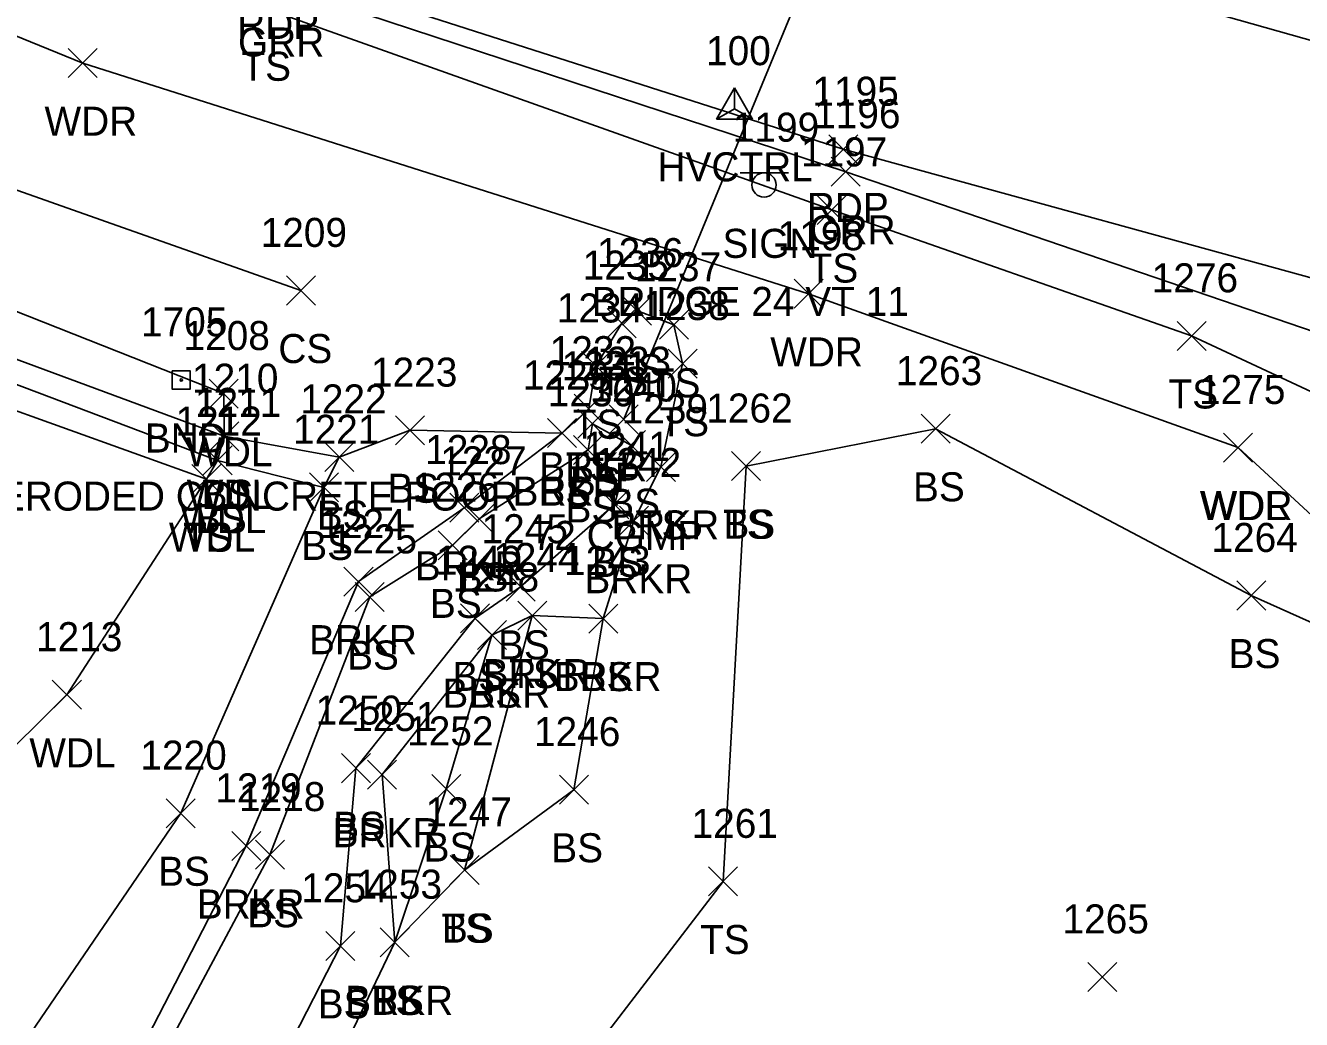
# Model space of a CAD drawing. Extents: x 1547013 to 1549434, y 267998 to 268739.
# Drawn here: x 1548511.9 to 1548599.8, y 268039.5 to 268107.9 of the extents above; entities that cross this region are included whole.
import ezdxf

# ---------------------------------------------------------------- set-up
doc = ezdxf.new("R2010")
doc.units = 0
for name, color, linetype in [('C_A', 7, 'Continuous'), ('C_I', 7, 'Continuous'), ('CPSM', 7, 'Continuous'), ('D_A', 7, 'Continuous'), ('D_C', 7, 'Continuous'), ('D_I', 7, 'Continuous'), ('D_TIC', 7, 'Continuous'), ('DCP', 7, 'Continuous'), ('L_A', 7, 'Continuous'), ('L_I', 7, 'Continuous'), ('L_TIC', 7, 'Continuous'), ('LAWA', 7, 'Continuous'), ('LAWE', 7, 'Continuous'), ('LELB', 7, 'Continuous'), ('M_A', 7, 'Continuous'), ('M_C', 7, 'Continuous'), ('M_I', 7, 'Continuous'), ('MHBP', 7, 'Continuous'), ('P_A', 7, 'Continuous'), ('P_I', 7, 'Continuous'), ('P_TIC', 7, 'Continuous'), ('PET', 7, 'Continuous'), ('PRC', 7, 'Continuous'), ('R_A', 7, 'Continuous'), ('R_I', 7, 'Continuous'), ('R_TIC', 7, 'Continuous'), ('RGR', 7, 'Continuous'), ('S_A', 7, 'Continuous'), ('S_C', 7, 'Continuous'), ('S_I', 7, 'Continuous'), ('SSGN', 7, 'Continuous')]:
    doc.layers.add(name, color=color, linetype=linetype)

msp = doc.modelspace()

# ---------------------------------------------------------------- linework, layer by layer
at = {"layer": 'CPSM'}
for p, q in [((1548559.462, 268101.487), (1548560.712, 268103.652)), ((1548559.462, 268101.487), (1548560.712, 268103.652)), ((1548561.962, 268101.487), (1548560.712, 268103.652)), ((1548560.713, 268102.208), (1548560.712, 268103.652)), ((1548561.962, 268101.487), (1548560.712, 268103.652)), ((1548560.713, 268102.208), (1548560.712, 268103.652)), ((1548559.462, 268101.487), (1548560.713, 268102.208)), ((1548559.462, 268101.487), (1548560.713, 268102.208)), ((1548560.713, 268102.208), (1548560.713, 268102.208)), ((1548560.713, 268102.208), (1548561.962, 268101.487)), ((1548560.713, 268102.208), (1548560.713, 268102.208)), ((1548560.713, 268102.208), (1548561.962, 268101.487)), ((1548559.462, 268101.487), (1548561.962, 268101.487)), ((1548559.462, 268101.487), (1548561.962, 268101.487))]:
    msp.add_line(p, q, dxfattribs=at)
at = {"layer": 'D_TIC'}
for points in [[(1548552.082, 268079.82), (1548554.082, 268081.82)], [(1548554.082, 268079.82), (1548552.082, 268081.82)]]:
    msp.add_lwpolyline(points, dxfattribs=at)
at = {"layer": 'DCP'}
msp.add_lwpolyline([(1548553.082, 268080.82), (1548581.569, 268149.791)], dxfattribs=at)
at = {"layer": 'L_TIC'}
for points in [[(1548514.817, 268104.352), (1548516.817, 268106.352)], [(1548516.817, 268104.352), (1548514.817, 268106.352)], [(1548566.412, 268094.236), (1548568.412, 268096.236)], [(1548568.412, 268094.236), (1548566.412, 268096.236)], [(1548529.847, 268088.689), (1548531.847, 268090.689)], [(1548531.847, 268088.689), (1548529.847, 268090.689)], [(1548564.814, 268088.461), (1548566.814, 268090.461)], [(1548566.814, 268088.461), (1548564.814, 268090.461)], [(1548552.994, 268087.3), (1548554.994, 268089.3)], [(1548554.994, 268087.3), (1548552.994, 268089.3)], [(1548551.944, 268086.439), (1548553.944, 268088.439)], [(1548553.944, 268086.439), (1548551.944, 268088.439)], [(1548555.538, 268086.326), (1548557.538, 268088.326)], [(1548557.538, 268086.326), (1548555.538, 268088.326)], [(1548591.201, 268085.561), (1548593.201, 268087.561)], [(1548593.201, 268085.561), (1548591.201, 268087.561)], [(1548550.163, 268083.485), (1548552.163, 268085.485)], [(1548552.163, 268083.485), (1548550.163, 268085.485)], [(1548556.133, 268083.65), (1548558.133, 268085.65)], [(1548558.133, 268083.65), (1548556.133, 268085.65)], [(1548524.525, 268081.584), (1548526.525, 268083.584)], [(1548526.525, 268081.584), (1548524.525, 268083.584)], [(1548549.675, 268080.543), (1548551.675, 268082.543)], [(1548551.675, 268080.543), (1548549.675, 268082.543)], [(1548549.675, 268080.543), (1548551.675, 268082.543)], [(1548551.675, 268080.543), (1548549.675, 268082.543)], [(1548537.362, 268079.066), (1548539.362, 268081.066)], [(1548539.362, 268079.066), (1548537.362, 268081.066)], [(1548549.929, 268079.508), (1548551.929, 268081.508)], [(1548551.929, 268079.508), (1548549.929, 268081.508)], [(1548573.568, 268079.167), (1548575.568, 268081.167)], [(1548575.568, 268079.167), (1548573.568, 268081.167)], [(1548524.556, 268078.648), (1548526.556, 268080.648)], [(1548526.556, 268078.648), (1548524.556, 268080.648)], [(1548524.556, 268078.648), (1548526.556, 268080.648)], [(1548526.556, 268078.648), (1548524.556, 268080.648)], [(1548547.832, 268078.869), (1548549.832, 268080.869)], [(1548549.832, 268078.869), (1548547.832, 268080.869)], [(1548547.832, 268078.869), (1548549.832, 268080.869)], [(1548549.832, 268078.869), (1548547.832, 268080.869)], [(1548532.489, 268077.219), (1548534.489, 268079.219)], [(1548534.489, 268077.219), (1548532.489, 268079.219)], [(1548532.489, 268077.219), (1548534.489, 268079.219)], [(1548534.489, 268077.219), (1548532.489, 268079.219)], [(1548549.63, 268077.711), (1548551.63, 268079.711)], [(1548551.63, 268077.711), (1548549.63, 268079.711)], [(1548552.575, 268078.042), (1548554.575, 268080.042)], [(1548554.575, 268078.042), (1548552.575, 268080.042)], [(1548594.409, 268077.871), (1548596.409, 268079.871)], [(1548596.409, 268077.871), (1548594.409, 268079.871)], [(1548594.409, 268077.871), (1548596.409, 268079.871)], [(1548596.409, 268077.871), (1548594.409, 268079.871)], [(1548524.104, 268076.981), (1548526.104, 268078.981)], [(1548526.104, 268076.981), (1548524.104, 268078.981)], [(1548524.104, 268076.981), (1548526.104, 268078.981)], [(1548526.104, 268076.981), (1548524.104, 268078.981)], [(1548554.64, 268076.538), (1548556.64, 268078.538)], [(1548556.64, 268076.538), (1548554.64, 268078.538)], [(1548554.64, 268076.538), (1548556.64, 268078.538)], [(1548556.64, 268076.538), (1548554.64, 268078.538)], [(1548560.508, 268076.593), (1548562.508, 268078.593)], [(1548562.508, 268076.593), (1548560.508, 268078.593)], [(1548560.508, 268076.593), (1548562.508, 268078.593)], [(1548562.508, 268076.593), (1548560.508, 268078.593)], [(1548523.33, 268075.697), (1548525.33, 268077.697)], [(1548525.33, 268075.697), (1548523.33, 268077.697)], [(1548523.33, 268075.697), (1548525.33, 268077.697)], [(1548525.33, 268075.697), (1548523.33, 268077.697)], [(1548531.424, 268075.127), (1548533.424, 268077.127)], [(1548533.424, 268075.127), (1548531.424, 268077.127)], [(1548531.424, 268075.127), (1548533.424, 268077.127)], [(1548533.424, 268075.127), (1548531.424, 268077.127)], [(1548541.097, 268073.729), (1548543.097, 268075.729)], [(1548543.097, 268073.729), (1548541.097, 268075.729)], [(1548551.435, 268073.954), (1548553.435, 268075.954)], [(1548553.435, 268073.954), (1548551.435, 268075.954)], [(1548542.133, 268072.957), (1548544.133, 268074.957)], [(1548544.133, 268072.957), (1548542.133, 268074.957)], [(1548552.783, 268072.836), (1548554.783, 268074.836)], [(1548554.783, 268072.836), (1548552.783, 268074.836)], [(1548540.29, 268071.138), (1548542.29, 268073.138)], [(1548542.29, 268071.138), (1548540.29, 268073.138)], [(1548533.81, 268068.637), (1548535.81, 268070.637)], [(1548535.81, 268068.637), (1548533.81, 268070.637)], [(1548534.584, 268067.58), (1548536.584, 268069.58)], [(1548536.584, 268067.58), (1548534.584, 268069.58)], [(1548544.979, 268068.28), (1548546.979, 268070.28)], [(1548546.979, 268068.28), (1548544.979, 268070.28)], [(1548595.314, 268067.68), (1548597.314, 268069.68)], [(1548597.314, 268067.68), (1548595.314, 268069.68)], [(1548541.836, 268066.108), (1548543.836, 268068.108)], [(1548543.836, 268066.108), (1548541.836, 268068.108)], [(1548545.778, 268066.299), (1548547.778, 268068.299)], [(1548547.778, 268066.299), (1548545.778, 268068.299)], [(1548545.778, 268066.299), (1548547.778, 268068.299)], [(1548547.778, 268066.299), (1548545.778, 268068.299)], [(1548550.667, 268066.092), (1548552.667, 268068.092)], [(1548552.667, 268066.092), (1548550.667, 268068.092)], [(1548550.667, 268066.092), (1548552.667, 268068.092)], [(1548552.667, 268066.092), (1548550.667, 268068.092)], [(1548542.997, 268064.954), (1548544.997, 268066.954)], [(1548544.997, 268064.954), (1548542.997, 268066.954)], [(1548542.997, 268064.954), (1548544.997, 268066.954)], [(1548544.997, 268064.954), (1548542.997, 268066.954)], [(1548513.716, 268060.844), (1548515.716, 268062.844)], [(1548515.716, 268060.844), (1548513.716, 268062.844)], [(1548533.631, 268055.786), (1548535.631, 268057.786)], [(1548535.631, 268055.786), (1548533.631, 268057.786)], [(1548535.438, 268055.344), (1548537.438, 268057.344)], [(1548537.438, 268055.344), (1548535.438, 268057.344)], [(1548539.853, 268054.353), (1548541.853, 268056.353)], [(1548541.853, 268054.353), (1548539.853, 268056.353)], [(1548548.648, 268054.306), (1548550.648, 268056.306)], [(1548550.648, 268054.306), (1548548.648, 268056.306)], [(1548521.561, 268052.685), (1548523.561, 268054.685)], [(1548523.561, 268052.685), (1548521.561, 268054.685)], [(1548526.076, 268050.43), (1548528.076, 268052.43)], [(1548528.076, 268050.43), (1548526.076, 268052.43)], [(1548527.703, 268049.828), (1548529.703, 268051.828)], [(1548529.703, 268049.828), (1548527.703, 268051.828)], [(1548541.115, 268048.77), (1548543.115, 268050.77)], [(1548543.115, 268048.77), (1548541.115, 268050.77)], [(1548541.115, 268048.77), (1548543.115, 268050.77)], [(1548543.115, 268048.77), (1548541.115, 268050.77)], [(1548558.928, 268047.986), (1548560.928, 268049.986)], [(1548560.928, 268047.986), (1548558.928, 268049.986)], [(1548532.559, 268043.548), (1548534.559, 268045.548)], [(1548534.559, 268043.548), (1548532.559, 268045.548)], [(1548536.305, 268043.796), (1548538.305, 268045.796)], [(1548538.305, 268043.796), (1548536.305, 268045.796)], [(1548536.305, 268043.796), (1548538.305, 268045.796)], [(1548538.305, 268043.796), (1548536.305, 268045.796)], [(1548536.305, 268043.796), (1548538.305, 268045.796)], [(1548538.305, 268043.796), (1548536.305, 268045.796)], [(1548585.051, 268041.405), (1548587.051, 268043.405)], [(1548587.051, 268041.405), (1548585.051, 268043.405)]]:
    msp.add_lwpolyline(points, dxfattribs=at)
at = {"layer": 'LAWA'}
for points in [[(1548421.128, 268144.607), (1548415.52, 268137.541), (1548414.051, 268129.031), (1548450.891, 268111.618), (1548480.872, 268100.254), (1548525.525, 268082.584), (1548525.556, 268079.648), (1548525.104, 268077.981), (1548524.33, 268076.697), (1548514.716, 268061.844), (1548494.628, 268042.02)], [(1548421.128, 268144.607), (1548456.376, 268129.208), (1548489.146, 268116.234), (1548515.817, 268105.352), (1548565.814, 268089.461), (1548595.409, 268078.871)], [(1548532.993, 268010.684), (1548542.298, 268026.004), (1548565.761, 268021.303), (1548592.567, 268010.464), (1548617.706, 268005.033), (1548639.26, 268030.863), (1548643.499, 268053.682), (1548616.029, 268059.847), (1548595.409, 268078.871)]]:
    msp.add_lwpolyline(points, dxfattribs=at)
at = {"layer": 'LAWE'}
for points in [[(1548514.299, 268026.679), (1548527.076, 268051.43), (1548534.81, 268069.637), (1548542.097, 268074.729), (1548548.832, 268079.869), (1548550.675, 268081.543)], [(1548555.64, 268077.538), (1548553.783, 268073.836), (1548551.667, 268067.092), (1548546.778, 268067.299), (1548543.997, 268065.954), (1548536.438, 268056.344), (1548537.305, 268044.796), (1548523.564, 268016.083)]]:
    msp.add_lwpolyline(points, dxfattribs=at)
at = {"layer": 'LELB'}
for points in [[(1548272.574, 268212.48), (1548289.144, 268210.265), (1548307.619, 268202.44), (1548323.104, 268196.351), (1548369.713, 268173.309), (1548388.458, 268161.701), (1548422.316, 268150.28), (1548459.33, 268134.327), (1548490.599, 268122.373), (1548528.336, 268109.134), (1548567.412, 268095.236), (1548592.201, 268086.561), (1548606.656, 268079.823), (1548620.32, 268072.147), (1548638.754, 268065.647), (1548644.399, 268061.614), (1548647.643, 268052.815), (1548649.602, 268041.052)], [(1548289.243, 268200.124), (1548292.106, 268199.387), (1548293.234, 268192.211), (1548309.742, 268172.031), (1548335.421, 268162.826), (1548365.097, 268153.15), (1548400.458, 268134.439), (1548414.416, 268125.575), (1548450.518, 268108.177), (1548480.176, 268096.435), (1548525.556, 268079.648), (1548533.489, 268078.219), (1548538.362, 268080.066), (1548548.832, 268079.869)], [(1548289.243, 268200.124), (1548291.099, 268191.138), (1548308.713, 268170.169), (1548334.154, 268160.773), (1548364.932, 268151.692), (1548400.572, 268132.645), (1548414.227, 268124.118), (1548450.607, 268106.016), (1548479.711, 268095.132), (1548525.104, 268077.981), (1548532.424, 268076.127)], [(1548306.427, 268199.286), (1548321.428, 268192.43), (1548332.784, 268181.901), (1548367.715, 268165.701), (1548391.941, 268148.156), (1548415.52, 268137.541), (1548452.826, 268119.091), (1548479.134, 268107.945), (1548530.847, 268089.689)], [(1548450.659, 268104.524), (1548479.47, 268092.8), (1548524.33, 268076.697)], [(1548550.675, 268081.543), (1548551.163, 268084.485), (1548552.944, 268087.439), (1548553.994, 268088.3), (1548556.538, 268087.326), (1548557.133, 268084.65), (1548555.64, 268077.538)], [(1548515.429, 268025.988), (1548528.703, 268050.828), (1548535.584, 268068.58), (1548541.29, 268072.138), (1548543.133, 268073.957), (1548550.63, 268078.711), (1548550.929, 268080.508), (1548553.575, 268079.042), (1548552.435, 268074.954), (1548545.979, 268069.28), (1548542.836, 268067.108), (1548534.631, 268056.786), (1548533.559, 268044.548), (1548520.536, 268019.117)], [(1548561.508, 268077.593), (1548574.568, 268080.167), (1548596.314, 268068.68), (1548616.029, 268059.847)], [(1548506.568, 268030.258), (1548522.561, 268053.685), (1548532.424, 268076.127), (1548533.489, 268078.219)], [(1548542.298, 268026.004), (1548559.928, 268048.986), (1548561.508, 268077.593)], [(1548546.778, 268067.299), (1548542.115, 268049.77), (1548537.305, 268044.796)], [(1548551.667, 268067.092), (1548549.648, 268055.306), (1548542.115, 268049.77)], [(1548543.997, 268065.954), (1548540.853, 268055.353), (1548537.305, 268044.796)]]:
    msp.add_lwpolyline(points, dxfattribs=at)
at = {"layer": 'MHBP'}
msp.add_lwpolyline([(1548521.972, 268084.153), (1548523.222, 268084.153), (1548523.222, 268082.903), (1548521.972, 268082.903)], close=True, dxfattribs=at)
msp.add_circle((1548522.597, 268083.528), 0.0833, dxfattribs=at)
at = {"layer": 'P_TIC'}
for points in [[(1548567.204, 268098.414), (1548569.204, 268100.414)], [(1548569.204, 268098.414), (1548567.204, 268100.414)]]:
    msp.add_lwpolyline(points, dxfattribs=at)
at = {"layer": 'PET'}
msp.add_lwpolyline([(1548277.306, 268222.575), (1548324.078, 268200.052), (1548370.888, 268177.556), (1548421.343, 268155.116), (1548457.655, 268139.547), (1548491.254, 268126.096), (1548528.961, 268112.016), (1548568.204, 268099.414), (1548604.277, 268089.494), (1548621.896, 268083.867), (1548638.117, 268079.829), (1548660.939, 268075.038), (1548683.04, 268070.809), (1548718.585, 268065.269), (1548750.02, 268060.75), (1548786.089, 268057.255), (1548817.997, 268054.361), (1548866.138, 268051.84)], dxfattribs=at)
at = {"layer": 'PRC'}
msp.add_lwpolyline([(1548285.227, 268237.15), (1548330.43, 268214.749), (1548376.37, 268192.576), (1548426.535, 268169.593), (1548464.29, 268153.498), (1548497.35, 268140.085), (1548534.695, 268126.495), (1548572.932, 268114.689), (1548608.018, 268104.772), (1548637.809, 268097.375), (1548663.07, 268091.687), (1548686.377, 268086.96), (1548723.692, 268081.048), (1548751.899, 268076.9), (1548786.742, 268073.357), (1548818.759, 268070.537), (1548866.796, 268068.078)], dxfattribs=at)
at = {"layer": 'R_TIC'}
for points in [[(1548567.381, 268096.865), (1548569.381, 268098.865)], [(1548569.381, 268096.865), (1548567.381, 268098.865)]]:
    msp.add_lwpolyline(points, dxfattribs=at)
at = {"layer": 'RGR'}
msp.add_lwpolyline([(1548388.796, 268165.086), (1548420.433, 268153.83), (1548460.749, 268137.248), (1548490.898, 268125.098), (1548529.021, 268110.805), (1548568.381, 268097.865), (1548602.59, 268086.187)], dxfattribs=at)
at = {"layer": 'SSGN'}
for p, q in [((1548561.105, 268097.79), (1548564.438, 268097.79)), ((1548562.751, 268096.956), (1548562.751, 268096.956))]:
    msp.add_line(p, q, dxfattribs=at)
msp.add_circle((1548562.751, 268096.956), 0.833, dxfattribs=at)

# ---------------------------------------------------------------- texts
at = {"layer": 'C_A'}
msp.add_text('HVCTRL', height=2, dxfattribs=at).set_placement((1548555.406, 268097.208))
msp.add_text('HVCTRL', height=2, dxfattribs=at).set_placement((1548555.406, 268097.208))
at = {"layer": 'C_I'}
msp.add_text('100', height=2, dxfattribs=at).set_placement((1548558.752, 268105.208))
msp.add_text('100', height=2, dxfattribs=at).set_placement((1548558.752, 268105.208))
at = {"layer": 'D_A'}
msp.add_text('P', height=2, dxfattribs=at).set_placement((1548552.46, 268075.82))
at = {"layer": 'D_C'}
msp.add_text('72 CGMP', height=2, dxfattribs=at).set_placement((1548546.807, 268071.82))
at = {"layer": 'D_I'}
msp.add_text('1233', height=2, dxfattribs=at).set_placement((1548550.39, 268083.82))
at = {"layer": 'L_A'}
for s, p in [('TS', (1548526.745, 268104.134)), ('WDR', (1548513.179, 268100.352)), ('TS', (1548565.822, 268090.236)), ('CS', (1548529.288, 268084.689)), ('WDR', (1548563.176, 268084.461)), ('TS', (1548552.403, 268083.3)), ('TS', (1548551.353, 268082.439)), ('TS', (1548554.947, 268082.326)), ('TS', (1548590.611, 268081.561)), ('TS', (1548549.573, 268079.485)), ('TS', (1548555.542, 268079.65)), ('WDL', (1548522.943, 268077.584)), ('BRKR', (1548547.265, 268076.543)), ('TS', (1548549.084, 268076.543)), ('BS', (1548549.37, 268075.508)), ('WDL', (1548522.973, 268074.648)), ('BS', (1548523.997, 268074.648)), ('BS', (1548536.803, 268075.066)), ('BRKR', (1548545.422, 268074.869)), ('BS', (1548547.273, 268074.869)), ('BS', (1548573.009, 268075.167)), ('BS', (1548549.071, 268073.711)), ('BS', (1548552.016, 268074.042)), ('WDR', (1548592.771, 268073.871)), ('WDL', (1548592.826, 268073.871)), ('WDL', (1548522.521, 268072.981)), ('BS', (1548523.545, 268072.981)), ('BS', (1548531.93, 268073.219)), ('BS', (1548531.93, 268073.219)), ('BRKR', (1548552.23, 268072.538)), ('TS', (1548554.049, 268072.538)), ('TS', (1548559.918, 268072.593)), ('BS', (1548559.949, 268072.593)), ('WDL', (1548521.747, 268071.697)), ('TS', (1548522.739, 268071.697)), ('BS', (1548530.865, 268071.127)), ('BS', (1548530.865, 268071.127)), ('BRKR', (1548538.687, 268069.729)), ('BS', (1548550.876, 268069.954)), ('BS', (1548541.574, 268068.957)), ('BRKR', (1548550.373, 268068.836)), ('BS', (1548539.731, 268067.138)), ('BRKR', (1548531.401, 268064.637)), ('BS', (1548544.42, 268064.28)), ('BS', (1548534.025, 268063.58)), ('BS', (1548594.755, 268063.68)), ('BRKR', (1548543.369, 268062.299)), ('TS', (1548545.188, 268062.299)), ('BS', (1548541.277, 268062.108)), ('BRKR', (1548548.257, 268062.092)), ('BS', (1548550.108, 268062.092)), ('BRKR', (1548540.588, 268060.954)), ('BS', (1548542.438, 268060.954)), ('WDL', (1548512.133, 268056.844)), ('BS', (1548533.072, 268051.786)), ('BRKR', (1548533.028, 268051.344)), ('BS', (1548539.294, 268050.353)), ('BS', (1548548.089, 268050.306)), ('BS', (1548521.002, 268048.685)), ('BRKR', (1548523.667, 268046.43)), ('BS', (1548527.144, 268045.828)), ('TS', (1548540.525, 268044.77)), ('BS', (1548540.556, 268044.77)), ('TS', (1548558.338, 268043.986)), ('BS', (1548532, 268039.548)), ('BRKR', (1548533.895, 268039.796)), ('TS', (1548535.714, 268039.796)), ('BS', (1548535.746, 268039.796))]:
    msp.add_text(s, height=2, dxfattribs=at).set_placement(p)
at = {"layer": 'L_I'}
for s, p in [('1197', (1548565.287, 268098.236)), ('1209', (1548528.068, 268092.689)), ('1198', (1548563.688, 268092.461)), ('1236', (1548551.246, 268091.3)), ('1235', (1548550.251, 268090.439)), ('1237', (1548553.845, 268090.326)), ('1276', (1548589.454, 268089.561)), ('1234', (1548548.47, 268087.485)), ('1238', (1548554.44, 268087.65)), ('1208', (1548522.754, 268085.584)), ('1232', (1548547.982, 268084.543)), ('1232', (1548547.982, 268084.543)), ('1231', (1548548.803, 268083.508)), ('1210', (1548523.344, 268082.648)), ('1210', (1548523.344, 268082.648)), ('1223', (1548535.67, 268083.066)), ('1229', (1548546.131, 268082.869)), ('1229', (1548546.131, 268082.869)), ('1263', (1548571.828, 268083.167)), ('1230', (1548547.85, 268081.711)), ('1240', (1548550.795, 268082.042)), ('1275', (1548592.716, 268081.871)), ('1275', (1548592.716, 268081.871)), ('1211', (1548523.545, 268080.981)), ('1211', (1548523.545, 268080.981)), ('1222', (1548530.796, 268081.219)), ('1222', (1548530.796, 268081.219)), ('1239', (1548552.939, 268080.538)), ('1239', (1548552.939, 268080.538)), ('1262', (1548558.768, 268080.593)), ('1262', (1548558.768, 268080.593)), ('1212', (1548522.204, 268079.697)), ('1212', (1548522.204, 268079.697)), ('1221', (1548530.298, 268079.127)), ('1221', (1548530.298, 268079.127)), ('1228', (1548539.404, 268077.729)), ('1241', (1548550.31, 268077.954)), ('1227', (1548540.44, 268076.957)), ('1242', (1548551.09, 268076.836)), ('1226', (1548538.542, 268075.138)), ('1224', (1548532.117, 268072.637)), ('1245', (1548543.286, 268072.28)), ('1225', (1548532.891, 268071.58)), ('1264', (1548593.574, 268071.68)), ('1244', (1548544.086, 268070.299)), ('1244', (1548544.086, 268070.299)), ('1249', (1548540.136, 268070.108)), ('1243', (1548548.974, 268070.092)), ('1243', (1548548.974, 268070.092)), ('1248', (1548541.305, 268068.954)), ('1248', (1548541.305, 268068.954)), ('1213', (1548512.59, 268064.844)), ('1250', (1548531.851, 268059.786)), ('1251', (1548534.312, 268059.344)), ('1252', (1548538.16, 268058.353)), ('1246', (1548546.9, 268058.306)), ('1220', (1548519.782, 268056.685)), ('1219', (1548524.943, 268054.43)), ('1218', (1548526.577, 268053.828)), ('1247', (1548539.422, 268052.77)), ('1247', (1548539.422, 268052.77)), ('1261', (1548557.755, 268051.986)), ('1254', (1548530.866, 268047.548)), ('1253', (1548534.612, 268047.796)), ('1253', (1548534.612, 268047.796)), ('1253', (1548534.612, 268047.796)), ('1265', (1548583.311, 268045.405))]:
    msp.add_text(s, height=2, dxfattribs=at).set_placement(p)
at = {"layer": 'M_A'}
msp.add_text('BND', height=2, dxfattribs=at).set_placement((1548520.085, 268078.528))
at = {"layer": 'M_C'}
msp.add_text('2 REBARS & ERODED CONCRETE POOR', height=2, dxfattribs=at).set_placement((1548493.534, 268074.528))
at = {"layer": 'M_I'}
msp.add_text('1705', height=2, dxfattribs=at).set_placement((1548519.825, 268086.528))
at = {"layer": 'P_A'}
for p in [(1548526.449, 268107.016), (1548565.693, 268094.414)]:
    msp.add_text('RDP', height=2, dxfattribs=at).set_placement(p)
at = {"layer": 'P_I'}
msp.add_text('1195', height=2, dxfattribs=at).set_placement((1548566.079, 268102.414))
at = {"layer": 'R_A'}
for p in [(1548526.51, 268105.805), (1548565.869, 268092.865)]:
    msp.add_text('GRR', height=2, dxfattribs=at).set_placement(p)
at = {"layer": 'R_I'}
msp.add_text('1196', height=2, dxfattribs=at).set_placement((1548566.2, 268100.865))
at = {"layer": 'S_A'}
msp.add_text('SIGN', height=2, dxfattribs=at).set_placement((1548559.889, 268091.936))
at = {"layer": 'S_C'}
msp.add_text('BRIDGE 24 VT 11', height=2, dxfattribs=at).set_placement((1548550.874, 268087.936))
at = {"layer": 'S_I'}
msp.add_text('1199', height=2, dxfattribs=at).set_placement((1548560.598, 268099.936))

doc.saveas('drawing.dxf')
